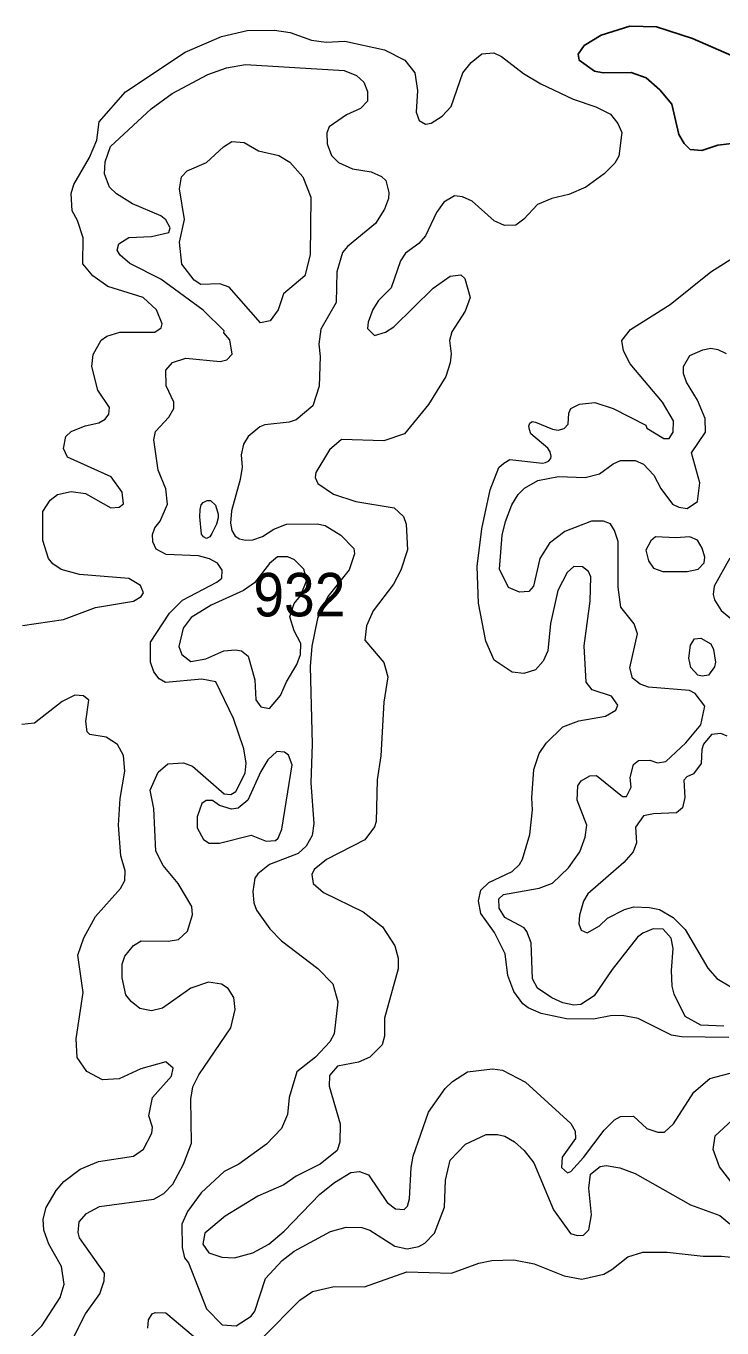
# Model space of a CAD drawing. Extents: x 763.2 to 816.8, y 7896.5 to 7952.7.
# Drawn here: x 766.518 to 769.081, y 7931.022 to 7935.819 of the extents above; entities that cross this region are included whole.
import ezdxf

# ---------------------------------------------------------------- set-up
doc = ezdxf.new("R2010")
doc.units = 0
doc.header["$LTSCALE"] = 0.064
doc.layers.add('1', color=7, linetype='Continuous', lineweight=25)
doc.layers.add('2', color=7, linetype='Continuous', lineweight=13)
doc.layers.add('21', color=7, linetype='Continuous')

msp = doc.modelspace()

# ---------------------------------------------------------------- linework, layer by layer
at = {"layer": '1'}
msp.add_lwpolyline([(769.288, 7935.6352), (768.9722, 7935.7728), (768.8392, 7935.816), (768.7413, 7935.819), (768.6355, 7935.7859), (768.5737, 7935.7467), (768.5509, 7935.7157), (768.5553, 7935.6928), (768.6106, 7935.653), (768.6427, 7935.6467), (768.7461, 7935.6484), (768.8009, 7935.628), (768.8514, 7935.5841), (768.8954, 7935.5313), (768.9222, 7935.4199), (768.9414, 7935.386), (768.9633, 7935.3643), (769.0069, 7935.3607), (769.0651, 7935.3806), (769.1365, 7935.3886)], dxfattribs=at)
at = {"layer": '2'}
for points in [[(766.505, 7933.6097), (766.6553, 7933.6329), (766.7738, 7933.6764), (766.9131, 7933.6993), (766.9413, 7933.7177), (766.9496, 7933.7309), (766.939, 7933.7577), (766.8959, 7933.7833), (766.7147, 7933.7976), (766.647, 7933.8162), (766.6164, 7933.8372), (766.6, 7933.8569), (766.5797, 7933.9233), (766.5788, 7934.0309), (766.6064, 7934.072), (766.6339, 7934.093), (766.6837, 7934.1034), (766.7363, 7934.0968), (766.8297, 7934.0441), (766.8599, 7934.0457), (766.877, 7934.0585), (766.8719, 7934.1013), (766.8305, 7934.1585), (766.6699, 7934.2311), (766.6559, 7934.2629), (766.6637, 7934.3067), (766.6842, 7934.3255), (766.735, 7934.3461), (766.7853, 7934.3564), (766.8093, 7934.371), (766.823, 7934.3888), (766.8249, 7934.4135), (766.7818, 7934.4778), (766.7603, 7934.5644), (766.7645, 7934.6086), (766.7939, 7934.6619), (766.8147, 7934.6766), (766.8624, 7934.6913), (766.9914, 7934.6916), (767.0156, 7934.7074), (767.0189, 7934.7219), (766.9982, 7934.7729), (766.9487, 7934.8193), (766.8186, 7934.8595), (766.7631, 7934.8983), (766.7272, 7934.9423), (766.7278, 7935.0392), (766.7072, 7935.103), (766.687, 7935.1378), (766.6838, 7935.2023), (766.6934, 7935.2351), (766.751, 7935.3343), (766.7782, 7935.398), (766.7874, 7935.4657), (766.8834, 7935.5762), (767.1033, 7935.7223), (767.2379, 7935.7808), (767.3324, 7935.8023), (767.4331, 7935.8042), (767.4902, 7935.7957), (767.5686, 7935.7665), (767.6231, 7935.7601), (767.6922, 7935.7632), (767.838, 7935.7318), (767.9126, 7935.693), (767.9493, 7935.646), (767.9589, 7935.5816), (767.9542, 7935.5015), (767.9656, 7935.4713), (767.9887, 7935.4578), (768.0094, 7935.4609), (768.0504, 7935.487), (768.083, 7935.5223), (768.1268, 7935.6466), (768.1567, 7935.6849), (768.1957, 7935.717), (768.2408, 7935.7205), (768.2691, 7935.7067), (768.3491, 7935.6446), (768.4137, 7935.6059), (768.5322, 7935.549), (768.6164, 7935.5217), (768.6698, 7935.494), (768.6966, 7935.4597), (768.7115, 7935.4264)], [(766.9417, 7932.4483), (767.0404, 7932.4469), (767.0786, 7932.4539), (767.1116, 7932.4841), (767.1307, 7932.5438), (767.1283, 7932.5743), (767.0777, 7932.6594), (767.0224, 7932.7263), (766.9956, 7932.7786), (766.9879, 7932.9357), (766.9746, 7933.0039), (767.0043, 7933.0697), (767.0398, 7933.1003), (767.097, 7933.1042), (767.1312, 7933.0914), (767.2477, 7932.9901), (767.2713, 7932.9877), (767.2898, 7932.9988), (767.3244, 7933.0667), (767.3279, 7933.1026), (767.32, 7933.1555), (767.2816, 7933.2675), (767.2161, 7933.4027), (767.1645, 7933.4131), (767.0311, 7933.4002), (767.0084, 7933.4141), (766.9878, 7933.4391), (766.9763, 7933.4747), (766.9765, 7933.5494), (767.0457, 7933.6552), (767.0942, 7933.7031), (767.2208, 7933.77), (767.2387, 7933.7848), (767.2403, 7933.8144), (767.2223, 7933.8402), (767.1935, 7933.8558), (767.1531, 7933.8667), (767.0331, 7933.8714), (766.9968, 7933.8909), (766.9843, 7933.9183), (766.9832, 7933.9455), (766.9924, 7933.9695), (767.0114, 7933.9947), (767.0386, 7934.0572), (767.0322, 7934.1143), (767.004, 7934.182), (766.988, 7934.2944), (766.9945, 7934.3251), (767.0436, 7934.3779), (767.0614, 7934.4101), (767.0615, 7934.4336), (767.0338, 7934.493), (767.0323, 7934.5513), (767.0564, 7934.5796), (767.1061, 7934.5952), (767.2325, 7934.5834), (767.2568, 7934.589), (767.2768, 7934.6095), (767.2676, 7934.6625), (767.2462, 7934.6888), (767.2469, 7934.6965), (767.1694, 7934.7726), (767.0134, 7934.886), (766.9002, 7934.944), (766.8643, 7934.9752), (766.8533, 7934.9931), (766.859, 7935.0165), (766.896, 7935.0395), (766.9795, 7935.0435), (767.0431, 7935.0583), (767.048, 7935.0752), (767.0325, 7935.1052), (767.0142, 7935.1197), (766.9099, 7935.1639), (766.8508, 7935.2004), (766.8246, 7935.2256), (766.8071, 7935.2744), (766.8089, 7935.3186), (766.8288, 7935.3756), (766.9779, 7935.5134), (767.0562, 7935.5706), (767.1866, 7935.64), (767.2563, 7935.6648), (767.3254, 7935.6778), (767.6895, 7935.6547), (767.7341, 7935.6373), (767.7618, 7935.6127), (767.7748, 7935.5776), (767.7747, 7935.5418), (767.7493, 7935.5152), (767.698, 7935.4913), (767.6337, 7935.4473), (767.6252, 7935.425), (767.626, 7935.3845), (767.6428, 7935.3424)], [(768.7115, 7935.4264), (768.7012, 7935.3397), (768.6866, 7935.3142), (768.6464, 7935.2741), (768.5796, 7935.2256), (768.5167, 7935.1983)], [(767.6428, 7935.3424), (767.6683, 7935.3166), (767.7198, 7935.2924), (767.7889, 7935.2823), (767.8273, 7935.2651), (767.8427, 7935.2494)], [(767.8427, 7935.2494), (767.8537, 7935.2061), (767.852, 7935.1833), (767.8374, 7935.1447), (767.8049, 7935.0918), (767.7016, 7935.0061), (767.6836, 7934.9849), (767.6616, 7934.9129), (767.6602, 7934.8003), (767.6036, 7934.7023), (767.5959, 7934.6474), (767.6008, 7934.6011), (767.5974, 7934.4925), (767.574, 7934.4197), (767.512, 7934.3681), (767.4865, 7934.3594), (767.3965, 7934.3495), (767.3783, 7934.3417), (767.3353, 7934.3061), (767.3179, 7934.2778), (767.3099, 7934.2391), (767.313, 7934.1931), (767.3065, 7934.1478), (767.2738, 7934.0327), (767.2706, 7933.9867), (767.2759, 7933.9602), (767.2872, 7933.9395), (767.3042, 7933.9294), (767.3259, 7933.9244), (767.3522, 7933.9264), (767.3885, 7933.9381), (767.4305, 7933.9656), (767.4768, 7933.9834), (767.5902, 7933.985), (767.6187, 7933.9784), (767.6766, 7933.9437), (767.7254, 7933.8944), (767.7271, 7933.8746), (767.7077, 7933.8148), (767.6292, 7933.717), (767.5911, 7933.6357), (767.5697, 7933.5338), (767.5645, 7933.4586), (767.571, 7933.1731), (767.5663, 7933.0302), (767.5776, 7932.8805), (767.5711, 7932.8364), (767.5497, 7932.7972), (767.5195, 7932.7704), (767.4148, 7932.7302), (767.3712, 7932.6956), (767.3603, 7932.6799), (767.3526, 7932.6307), (767.3562, 7932.5879), (767.3667, 7932.5618), (767.4155, 7932.4922), (767.4589, 7932.4486), (767.5925, 7932.3465), (767.6479, 7932.2896), (767.6663, 7932.2232), (767.652, 7932.1062), (767.6358, 7932.0759), (767.5831, 7932.02), (767.5153, 7931.9658), (767.4861, 7931.871), (767.4809, 7931.8091), (767.4584, 7931.7573), (767.4029, 7931.6987), (767.3016, 7931.6255), (767.2474, 7931.5986), (767.1627, 7931.5203), (767.1126, 7931.4515), (767.0916, 7931.4039), (767.093, 7931.3185), (767.1011, 7931.2807), (767.1156, 7931.2618), (767.1827, 7931.0925), (767.2393, 7931.0333), (767.2911, 7931.0303), (767.347, 7931.0659), (767.3597, 7931.0843), (767.3996, 7931.2046), (767.4605, 7931.2711), (767.5055, 7931.3046), (767.6383, 7931.3774), (767.6967, 7931.3934), (767.7538, 7931.392), (767.7843, 7931.3819), (767.8754, 7931.3235), (767.9213, 7931.313), (767.9639, 7931.3221), (767.9857, 7931.335), (768.0221, 7931.3717), (768.0585, 7931.4668), (768.0624, 7931.5662)], [(768.5167, 7935.1983), (768.4542, 7935.1838), (768.4015, 7935.1618), (768.3512, 7935.1071), (768.3218, 7935.0852), (768.2803, 7935.0843), (768.2414, 7935.1011), (768.1607, 7935.1738), (768.1246, 7935.1892), (768.0961, 7935.1928), (768.0558, 7935.1695), (768.0294, 7935.1314), (767.9882, 7935.0462), (767.9638, 7935.0172), (767.9155, 7934.9819), (767.8972, 7934.9542), (767.8617, 7934.854), (767.8153, 7934.8077), (767.7944, 7934.775), (767.7772, 7934.7285), (767.7749, 7934.7049), (767.8005, 7934.6788), (767.842, 7934.6908), (767.8723, 7934.7103), (768.0176, 7934.8532), (768.0801, 7934.8968), (768.1183, 7934.9018), (768.1337, 7934.8887), (768.1528, 7934.8184), (768.1351, 7934.7682), (768.0855, 7934.6928), (768.0774, 7934.6599), (768.0838, 7934.6112), (768.0802, 7934.5779), (768.0633, 7934.5272), (768.0001, 7934.424), (767.9117, 7934.3161), (767.8348, 7934.2909), (767.6798, 7934.2955), (767.6353, 7934.2579), (767.5844, 7934.1741), (767.5827, 7934.1555), (767.5926, 7934.1331), (767.6498, 7934.0946), (767.7323, 7934.0673), (767.8729, 7934.0444), (767.9074, 7934.0119), (767.9177, 7933.9834), (767.9228, 7933.8888), (767.8983, 7933.8147), (767.8712, 7933.7622), (767.7964, 7933.6646), (767.7713, 7933.6091), (767.7652, 7933.5568), (767.8356, 7933.4739), (767.8504, 7933.4214), (767.8356, 7933.3278), (767.8242, 7933.1295), (767.8113, 7933.0416), (767.8076, 7932.8883), (767.8004, 7932.868), (767.7654, 7932.8201), (767.6244, 7932.7479), (767.5783, 7932.7115), (767.5699, 7932.6928), (767.5751, 7932.6599), (767.6133, 7932.626), (767.7595, 7932.555), (767.8307, 7932.4994), (767.8762, 7932.4303), (767.888, 7932.3842), (767.8885, 7932.3457), (767.8382, 7932.163), (767.8374, 7932.0976), (767.8297, 7932.0658), (767.7837, 7932.02), (767.7414, 7932.0013), (767.6644, 7931.987), (767.6355, 7931.952), (767.6339, 7931.9123), (767.6747, 7931.7739), (767.6731, 7931.7071), (767.6636, 7931.6755), (767.6006, 7931.6253), (767.5122, 7931.5807), (767.4667, 7931.5499), (767.3716, 7931.5071), (767.2503, 7931.4336), (767.1765, 7931.3712), (767.1688, 7931.331), (767.1904, 7931.2991), (767.2392, 7931.2833), (767.2858, 7931.28), (767.3528, 7931.2993), (767.4117, 7931.3311)], [(768.4201, 7934.2088), (768.4307, 7934.2111), (768.4413, 7934.2158), (768.4499, 7934.225), (768.4516, 7934.2346), (768.4485, 7934.2497), (768.4394, 7934.2636), (768.3769, 7934.3168), (768.3713, 7934.3325), (768.3699, 7934.3453), (768.3736, 7934.356), (768.3821, 7934.3614), (768.3935, 7934.3594), (768.456, 7934.3335), (768.4771, 7934.3297), (768.4998, 7934.3366), (768.5145, 7934.3524), (768.5168, 7934.3931), (768.524, 7934.4097), (768.5563, 7934.4259), (768.6124, 7934.4321), (768.6794, 7934.4104), (768.7998, 7934.3482), (768.8038, 7934.3372), (768.8669, 7934.299), (768.886, 7934.299), (768.901, 7934.3226), (768.9022, 7934.364), (768.8612, 7934.4337), (768.7423, 7934.5738), (768.7178, 7934.6226), (768.7119, 7934.6598), (768.7438, 7934.7007), (768.8898, 7934.7925), (769.0399, 7934.9132), (769.1465, 7934.9813)], [(768.9478, 7933.1776), (769.0025, 7933.2446), (769.0173, 7933.3129), (768.9814, 7933.36), (768.9614, 7933.3704), (768.8104, 7933.3835), (768.7788, 7933.3944), (768.7509, 7933.4163), (768.7414, 7933.4543), (768.7692, 7933.5794), (768.7574, 7933.6168), (768.7085, 7933.6772), (768.6986, 7933.7519), (768.6986, 7933.9196), (768.6854, 7933.9602), (768.6701, 7933.9848), (768.6445, 7933.9949), (768.6007, 7933.9949), (768.5019, 7933.9571), (768.4452, 7933.9137), (768.4104, 7933.8571), (768.3867, 7933.7548), (768.3697, 7933.7354), (768.3345, 7933.7336), (768.295, 7933.7499), (768.2616, 7933.8176), (768.2717, 7933.9426), (768.283, 7933.9939), (768.3063, 7934.0544), (768.3305, 7934.0935), (768.3535, 7934.1167), (768.4021, 7934.1443), (768.479, 7934.1592), (768.5763, 7934.1561), (768.6295, 7934.1693), (768.6803, 7934.2058), (768.7072, 7934.2178), (768.7604, 7934.2184), (768.792, 7934.2049), (768.8296, 7934.1646), (768.8556, 7934.1152), (768.8987, 7934.0578), (768.9221, 7934.0462), (768.952, 7934.041), (768.9905, 7934.067), (768.9992, 7934.1359), (768.9684, 7934.2462), (769.0204, 7934.3226), (769.0192, 7934.3732), (768.9911, 7934.4403), (768.95, 7934.5066), (768.9387, 7934.539), (768.9385, 7934.5641), (768.9624, 7934.6054), (769.0097, 7934.6265), (769.0398, 7934.6324), (769.0654, 7934.6278), (769.096, 7934.6124)], [(768.1958, 7933.967), (768.2265, 7934.1101), (768.2584, 7934.192), (768.2774, 7934.2089), (768.2994, 7934.2215), (768.4201, 7934.2088)], [(769.1054, 7932.0918), (768.9319, 7932.0952), (768.8948, 7932.1013), (768.7715, 7932.1622), (768.7131, 7932.1738), (768.6697, 7932.1723), (768.6076, 7932.1597), (768.5086, 7932.1609), (768.4153, 7932.1808), (768.3663, 7932.2012), (768.3476, 7932.2164), (768.3138, 7932.2618), (768.2925, 7932.321), (768.2822, 7932.4006), (768.243, 7932.479), (768.1931, 7932.5491), (768.1843, 7932.5959), (768.1923, 7932.6351), (768.2221, 7932.6636), (768.3079, 7932.7038), (768.3346, 7932.7293), (768.3461, 7932.7497), (768.3731, 7932.8403), (768.383, 7932.9316), (768.3798, 7932.9751), (768.388, 7933.0795), (768.4074, 7933.1381), (768.4331, 7933.1769), (768.4949, 7933.2372), (768.5533, 7933.2584), (768.6519, 7933.2766), (768.6896, 7933.2978), (768.6967, 7933.3165), (768.6744, 7933.3494), (768.602, 7933.3737), (768.5804, 7933.4009), (768.5737, 7933.5357), (768.5952, 7933.7), (768.5982, 7933.7901), (768.5895, 7933.8098), (768.5675, 7933.8268), (768.5354, 7933.8275), (768.5102, 7933.806), (768.4763, 7933.7397), (768.4487, 7933.6179), (768.4391, 7933.5174), (768.4223, 7933.479), (768.394, 7933.4471), (768.351, 7933.433), (768.308, 7933.4389), (768.2418, 7933.4831), (768.2105, 7933.5529), (768.1839, 7933.6924), (768.1793, 7933.8272), (768.1958, 7933.967)], [(769.1091, 7933.8579), (769.0524, 7933.7546), (769.0486, 7933.7249), (769.0534, 7933.7047), (769.0779, 7933.6654), (769.1206, 7933.6299)], [(766.6503, 7933.3298), (766.5491, 7933.2506), (766.5023, 7933.2457)], [(766.743, 7933.2182), (766.738, 7933.257), (766.7494, 7933.3346), (766.7294, 7933.3517), (766.6971, 7933.3538), (766.6503, 7933.3298)], [(766.5339, 7930.9886), (766.5755, 7931.0302), (766.6429, 7931.1343), (766.6574, 7931.1837), (766.6477, 7931.2481), (766.6018, 7931.3303), (766.5836, 7931.3829), (766.5802, 7931.4229), (766.5921, 7931.4663), (766.6279, 7931.5281), (766.6564, 7931.5614), (766.7163, 7931.6074), (766.7845, 7931.6354), (766.913, 7931.6548), (766.9497, 7931.6809), (766.9811, 7931.7392), (766.9828, 7931.7621), (766.9697, 7931.8036), (766.9838, 7931.8711), (767.0537, 7931.95), (767.06, 7931.9797), (767.0325, 7932.0027), (766.9401, 7931.9768), (766.8606, 7931.9405), (766.7992, 7931.936), (766.7418, 7931.9675), (766.7061, 7932.0189), (766.7019, 7932.0876), (766.7281, 7932.258), (766.7086, 7932.3954), (766.73, 7932.4589), (766.7739, 7932.5376), (766.8652, 7932.6414), (766.8809, 7932.6705), (766.8825, 7932.7068), (766.8662, 7932.7614), (766.8581, 7932.8745), (766.8643, 7932.9731), (766.8809, 7933.0731), (766.876, 7933.1314), (766.8547, 7933.1715), (766.8123, 7933.1992), (766.7526, 7933.209), (766.743, 7933.2182)], [(769.0994, 7933.2026), (769.0764, 7933.2125), (769.0424, 7933.2082), (769.0132, 7933.1728), (769.006, 7933.1531), (769.0042, 7933.1022), (768.976, 7933.0633), (768.9518, 7933.0531), (768.9405, 7933.04), (768.9434, 7932.9769), (768.9354, 7932.9387), (768.9127, 7932.9204), (768.8279, 7932.9164), (768.7916, 7932.9088), (768.7627, 7932.8667), (768.7656, 7932.8094), (768.7534, 7932.7769), (768.7196, 7932.7375), (768.5869, 7932.621), (768.5705, 7932.594), (768.5555, 7932.5431), (768.554, 7932.5116), (768.5615, 7932.4875), (768.584, 7932.4784), (768.6298, 7932.5036), (768.6596, 7932.532), (768.7212, 7932.5638), (768.7559, 7932.5732), (768.8136, 7932.5717), (768.8503, 7932.5633), (768.9006, 7932.5339), (768.9451, 7932.4898), (769.0281, 7932.3479), (769.0622, 7932.3099), (769.1134, 7932.279)], [(768.7551, 7933.0978), (768.7734, 7933.1126), (768.8153, 7933.114), (768.8431, 7933.1043), (768.8738, 7933.1089), (768.9478, 7933.1776)], [(769.0872, 7932.1343), (769.0027, 7932.138), (768.9449, 7932.1699), (768.9052, 7932.2523), (768.8975, 7932.2815), (768.8943, 7932.3394), (768.9006, 7932.4196), (768.8939, 7932.4582), (768.8636, 7932.491), (768.8274, 7932.4928), (768.7887, 7932.4771), (768.7692, 7932.4615), (768.6765, 7932.3429), (768.6101, 7932.2454), (768.5613, 7932.2135), (768.5347, 7932.2119), (768.4948, 7932.2201), (768.4538, 7932.2378), (768.4007, 7932.2738), (768.3832, 7932.308), (768.3781, 7932.4405), (768.3622, 7932.4832), (768.3517, 7932.4958), (768.2813, 7932.5344), (768.2602, 7932.5693), (768.2584, 7932.6027), (768.276, 7932.6189), (768.4078, 7932.6421), (768.4564, 7932.6613), (768.515, 7932.7169), (768.5573, 7932.7761), (768.5771, 7932.8304), (768.5834, 7932.8743), (768.5476, 7932.9671), (768.5502, 7933.0194), (768.5623, 7933.0383), (768.594, 7933.0561), (768.619, 7933.058), (768.7144, 7932.9798), (768.7295, 7932.9797), (768.746, 7933.0141), (768.7431, 7933.0507), (768.7551, 7933.0978)], [(766.8847, 7932.2495), (766.8711, 7932.3123), (766.8711, 7932.3619), (766.8808, 7932.3919), (766.9127, 7932.431), (766.9417, 7932.4483)], [(766.6594, 7930.9207), (766.7366, 7931.0743), (766.7893, 7931.1478), (766.8055, 7931.1954), (766.8069, 7931.2245), (766.715, 7931.354), (766.7101, 7931.3743), (766.7135, 7931.4129), (766.7398, 7931.4441), (766.7876, 7931.47), (766.9888, 7931.4969), (767.0251, 7931.518), (767.058, 7931.5515), (767.0977, 7931.6252), (767.1275, 7931.703), (767.1242, 7931.8649), (767.1313, 7931.9108), (767.1534, 7931.9548), (767.2715, 7932.128), (767.2879, 7932.1951), (767.2823, 7932.24), (767.2619, 7932.2723), (767.2377, 7932.2893), (767.1901, 7932.2957), (767.1242, 7932.2741), (767.0196, 7932.2008), (766.98, 7932.1909), (766.9371, 7932.1996), (766.9048, 7932.2247), (766.8847, 7932.2495)], [(767.7452, 7931.5987), (767.7789, 7931.5859), (767.8473, 7931.4838), (767.8786, 7931.4609), (767.9106, 7931.4584), (767.9227, 7931.4709), (767.9298, 7931.4976), (767.9361, 7931.6136), (767.9439, 7931.6548), (768.0002, 7931.8174), (768.0607, 7931.9042), (768.0878, 7931.9295), (768.1432, 7931.9652), (768.2351, 7931.9768), (768.2727, 7931.9716), (768.3567, 7931.9275), (768.5237, 7931.7751), (768.5405, 7931.747), (768.5406, 7931.7195), (768.4915, 7931.6516), (768.4902, 7931.6138), (768.5113, 7931.5941), (768.5236, 7931.5983), (768.5703, 7931.6498), (768.6465, 7931.7506), (768.685, 7931.7889), (768.707, 7931.8007), (768.7544, 7931.8024), (768.8039, 7931.7568), (768.845, 7931.7438), (768.8694, 7931.7438), (768.9027, 7931.7738), (768.9771, 7931.8913), (769.0358, 7931.9415), (769.1291, 7931.9653)], [(769.1849, 7931.469), (769.0719, 7931.6158), (769.0487, 7931.68), (769.055, 7931.7299), (769.1177, 7931.7877)], [(768.0624, 7931.5662), (768.0802, 7931.6405), (768.1355, 7931.6994), (768.2121, 7931.7352), (768.2541, 7931.7352), (768.2806, 7931.7286)], [(768.2806, 7931.7286), (768.3161, 7931.7074), (768.3522, 7931.6755), (768.388, 7931.631), (768.46, 7931.457), (768.5229, 7931.3705), (768.5478, 7931.3622), (768.5702, 7931.3641), (768.5902, 7931.3833), (768.5999, 7931.4394), (768.5902, 7931.5366), (768.5969, 7931.5882), (768.6321, 7931.6164), (768.654, 7931.62), (768.7042, 7931.6122), (768.761, 7931.5906), (768.9645, 7931.4757), (769.0732, 7931.436), (769.1092, 7931.4051)], [(767.4117, 7931.3311), (767.4681, 7931.3792), (767.5996, 7931.5155), (767.6537, 7931.5585), (767.7139, 7931.5942), (767.7452, 7931.5987)], [(767.3871, 7930.9842), (767.5263, 7931.125), (767.5722, 7931.1564), (767.652, 7931.1747), (767.7641, 7931.1739), (767.9196, 7931.2289), (768.0851, 7931.2243), (768.1847, 7931.2607), (768.2325, 7931.2701), (768.314, 7931.2734), (768.389, 7931.2588), (768.4994, 7931.2138), (768.5645, 7931.2012), (768.6454, 7931.2206), (768.6749, 7931.237), (768.7335, 7931.2844), (768.7897, 7931.3015), (768.8793, 7931.3013), (769.0115, 7931.2866), (769.0792, 7931.2865), (769.3073, 7931.2638)], [(766.9666, 7931.0214), (766.968, 7931.0525), (766.9826, 7931.0737), (766.9934, 7931.0792), (767.0326, 7931.0775), (767.1797, 7930.9538)]]:
    msp.add_lwpolyline(points, dxfattribs=at)
for points in [[(767.266, 7934.8564), (767.2311, 7934.8692), (767.1619, 7934.8669), (767.1368, 7934.8832), (767.0919, 7934.9422), (767.0831, 7935.0221), (767.1012, 7935.106), (767.0831, 7935.2187), (767.0898, 7935.263), (767.1113, 7935.2855), (767.1826, 7935.3159), (767.2442, 7935.3738), (767.2754, 7935.3933), (767.3211, 7935.39), (767.3742, 7935.3592), (767.4482, 7935.3414), (767.489, 7935.3179), (767.5366, 7935.2636), (767.5664, 7935.1884), (767.5645, 7934.9761), (767.5438, 7934.8987), (767.4661, 7934.8329), (767.4464, 7934.773), (767.4161, 7934.7329), (767.3808, 7934.725)], [(767.1826, 7933.9311), (767.1709, 7933.9367), (767.1641, 7933.947), (767.1571, 7934.0112), (767.1587, 7934.0382), (767.1626, 7934.0553), (767.1695, 7934.0637), (767.1842, 7934.071), (767.1975, 7934.0703), (767.2155, 7934.0538), (767.2249, 7934.0205), (767.2257, 7934.0073), (767.2185, 7933.9833), (767.2012, 7933.949), (767.1945, 7933.9372)], [(768.863, 7933.8098), (768.9523, 7933.8093), (768.9934, 7933.8173), (769.0151, 7933.8417), (769.0172, 7933.8618), (769.0073, 7933.8957), (768.9908, 7933.9241), (768.9624, 7933.9374), (768.9109, 7933.9327), (768.8356, 7933.9373), (768.8186, 7933.9225), (768.8005, 7933.8875), (768.8104, 7933.8488), (768.8282, 7933.8213)], [(767.5281, 7933.7201), (767.5514, 7933.7768), (767.5404, 7933.818), (767.5058, 7933.8524), (767.4814, 7933.8633), (767.4432, 7933.8631), (767.4146, 7933.8382), (767.3584, 7933.7674), (767.3185, 7933.7388), (767.1991, 7933.6855), (767.1253, 7933.6393), (767.0966, 7933.601), (767.0805, 7933.5332), (767.0916, 7933.5029), (767.1248, 7933.4779), (767.1795, 7933.4876), (767.2459, 7933.5172), (767.2888, 7933.5211), (767.3113, 7933.5167), (767.3358, 7933.4978), (767.3604, 7933.4104), (767.3641, 7933.3369), (767.3819, 7933.3108), (767.4142, 7933.3049), (767.4547, 7933.3529), (767.4762, 7933.4023), (767.5154, 7933.4664), (767.5281, 7933.5029), (767.5298, 7933.544), (767.5049, 7933.5903), (767.4889, 7933.6427), (767.5055, 7933.6909)], [(768.9666, 7933.4549), (768.9583, 7933.4905), (768.9642, 7933.5376), (768.9798, 7933.5608), (769.0024, 7933.5641), (769.0391, 7933.5423), (769.0498, 7933.5219), (769.0567, 7933.4747), (769.0536, 7933.4582), (769.0307, 7933.427), (769.0076, 7933.4231), (768.9916, 7933.4277)], [(767.4972, 7933.0965), (767.4842, 7933.1319), (767.4692, 7933.1435), (767.4411, 7933.1457), (767.4081, 7933.1151), (767.3817, 7933.0722), (767.3338, 7932.9666), (767.2989, 7932.9371), (767.2742, 7932.9333), (767.2303, 7932.9475), (767.2047, 7932.9659), (767.1808, 7932.966), (767.1649, 7932.9542), (767.1472, 7932.9053), (767.1472, 7932.8653), (767.1712, 7932.8223), (767.1925, 7932.8084), (767.2298, 7932.8086), (767.3461, 7932.8378), (767.4021, 7932.8153), (767.436, 7932.8186), (767.4456, 7932.8263), (767.4592, 7932.8596)]]:
    msp.add_lwpolyline(points, close=True, dxfattribs=at)

# ---------------------------------------------------------------- texts
at = {"layer": '21', "width": 0.95}
msp.add_text('932', height=0.16, dxfattribs=at).set_placement((767.3546, 7933.6439))

doc.saveas('drawing.dxf')
